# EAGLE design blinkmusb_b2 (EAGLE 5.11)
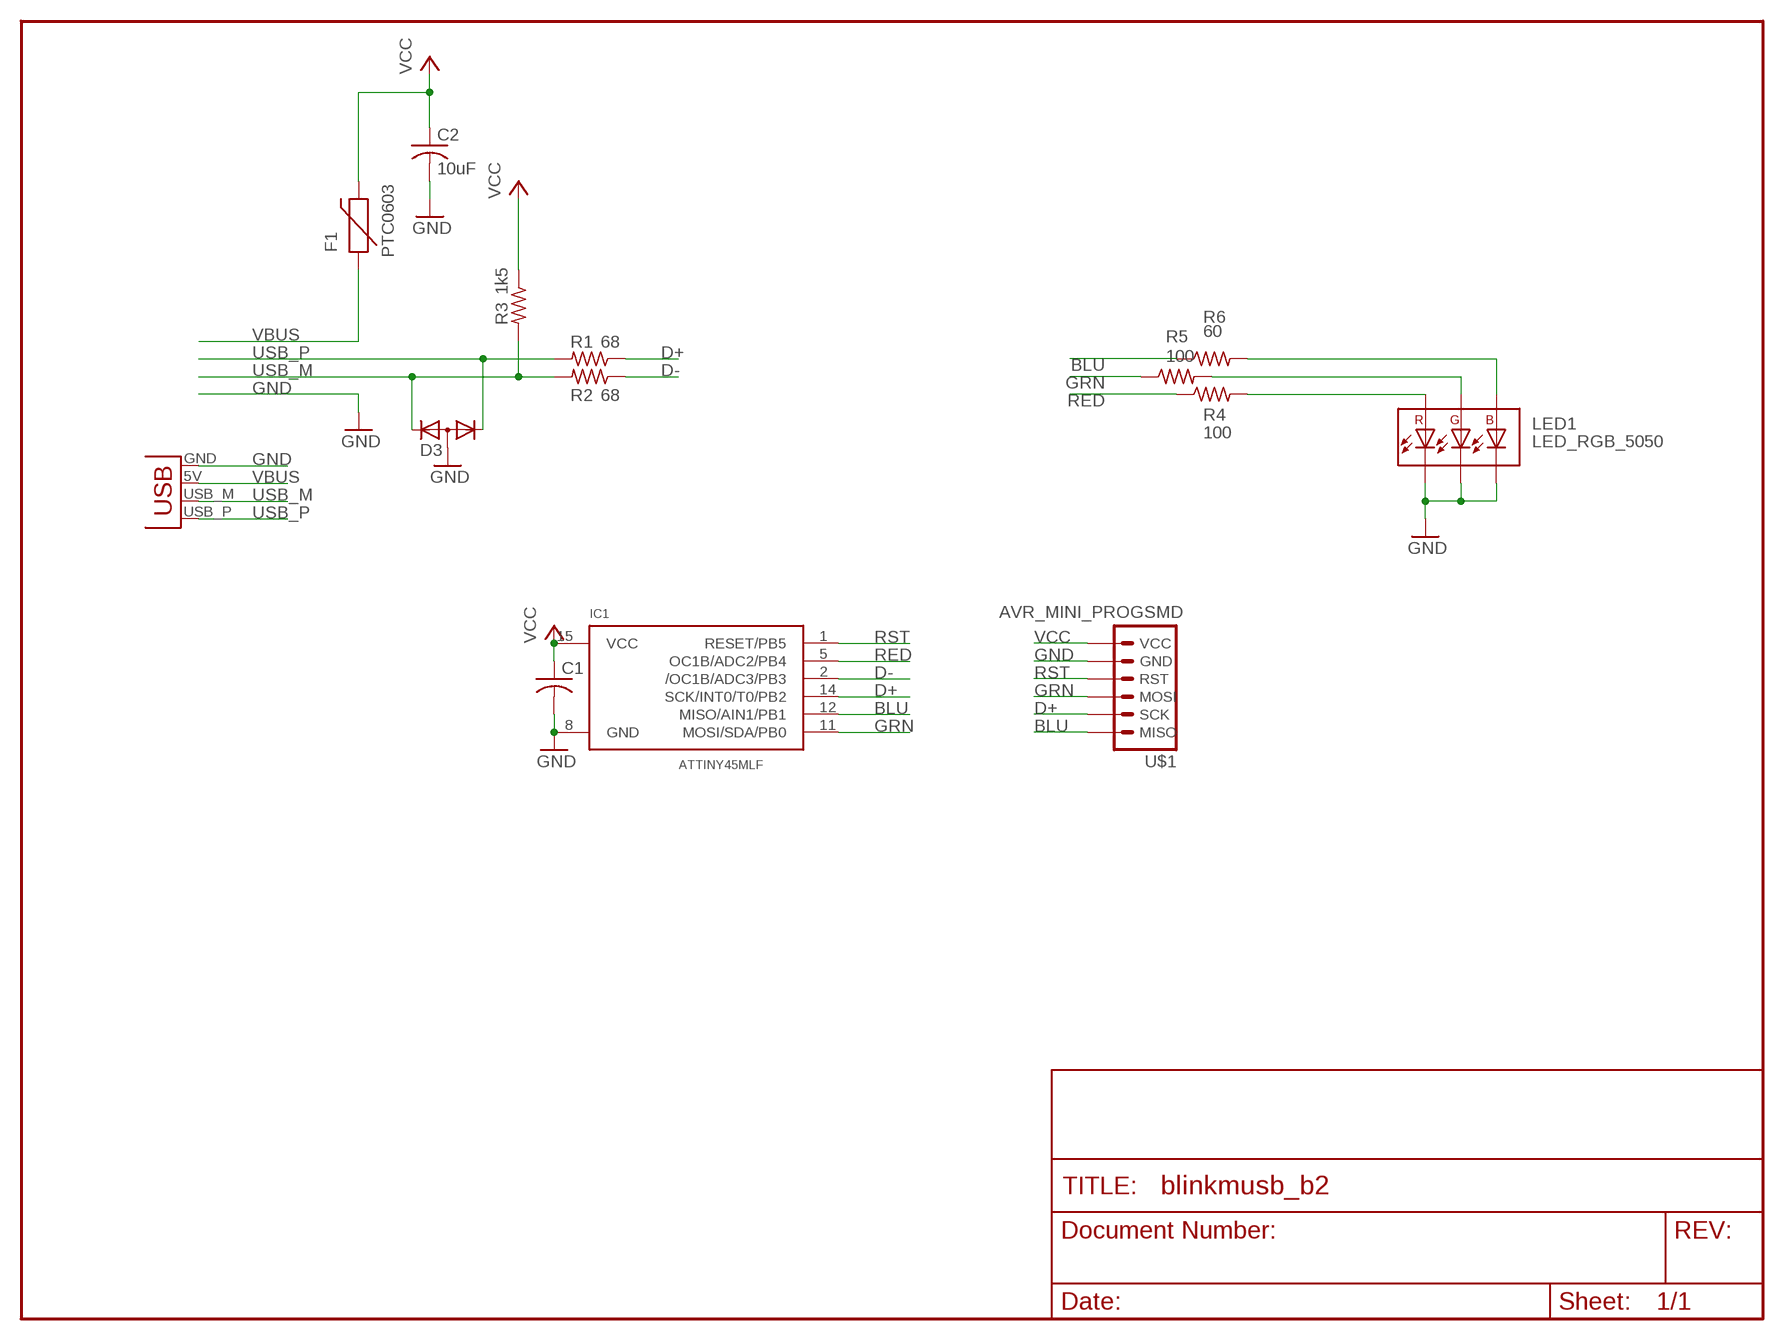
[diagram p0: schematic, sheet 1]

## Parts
C1  C-USC0603  [C0603]
C2  10uF  C-USC0805  [C0805]
D3  DIODE-2CA|ACSOT23  [SOT23]
F1  PTC0603  [0603]
IC1  ATTINY45MLF  [MLF20]
LED1  LED_RGB_5050  [LED_5050]
R1  68  R-US_R0603  [R0603]
R2  68  R-US_R0603  [R0603]
R3  1k5  R-US_R0603  [R0603]
R4  100  R-US_R0603  [R0603]
R5  100  R-US_R0603  [R0603]
R6  60  R-US_R0603  [R0603]
U$1  AVR_MINI_PROGSMD  [AVR_MINI_PROG]
X2  USBPCB  [USB-A-PCB]

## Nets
BLU: IC1.12(MISO/AIN1/PB1) R6.1 U$1.6(MISO)
D+: IC1.14(SCK/INT0/T0/PB2) R1.1 U$1.5(SCK)
D-: IC1.2(/OC1B/ADC3/PB3) R2.1
GND: C1.2 C2.2 D3.3(A) IC1.8(GND) LED1.P$4(C2) LED1.P$5(C1) LED1.P$6(C0) U$1.2(GND) X2.GND
GRN: IC1.11(MOSI/SDA/PB0) R5.1 U$1.4(MOSI)
RBLU: LED1.P$3(A2) R6.2
RED: IC1.5(OC1B/ADC2/PB4) R4.1
RGRN: LED1.P$2(A1) R5.2
RRED: LED1.P$1(A0) R4.2
RST: IC1.1(RESET/PB5) U$1.3(RST)
USB_M: D3.2(K2) R2.2 R3.2 X2.USB_M(D-)
USB_P: D3.1(K1) R1.2 X2.USB_P(D+)
VBUS: F1.1 X2.5V(VBUS)
VCC: C1.1 C2.1 F1.2 IC1.15(VCC) R3.1 U$1.1(VCC)

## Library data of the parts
C1 C2 = rcl:C-US: CAPACITOR, American symbol
D3 = diode:DIODE-2CA|AC: Dual DIODE Cathode-Anode|Anode-Cathode
F1 = SparkFun-20110517:PTC: Resettable Fuse PTC
IC1 = todstuff:ATTINY45
LED1 = todstuff:LED_RGB_5050
R1-R6 = rcl:R-US_: RESISTOR, American symbol
U$1 = SparkFun-20110517:AVR_MINI_PROG
X2 = SparkFun-20110517:USB: USB Connectors USB-B-PTH is fully proven SKU : PRT-00139 USB-miniB is fully proven SKU : PRT-00587 USB-A-PCB is untested. USB-A-H is throughly reviewed, but untested. Spark Fun Electronics SKU : PRT-00437 USB-B-SMT is throughly reviewed, but untested. Needs silkscreen touching up. USB-A-S has not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

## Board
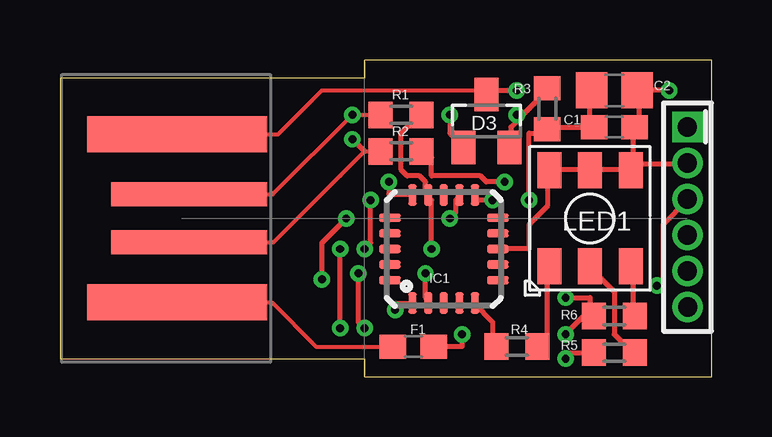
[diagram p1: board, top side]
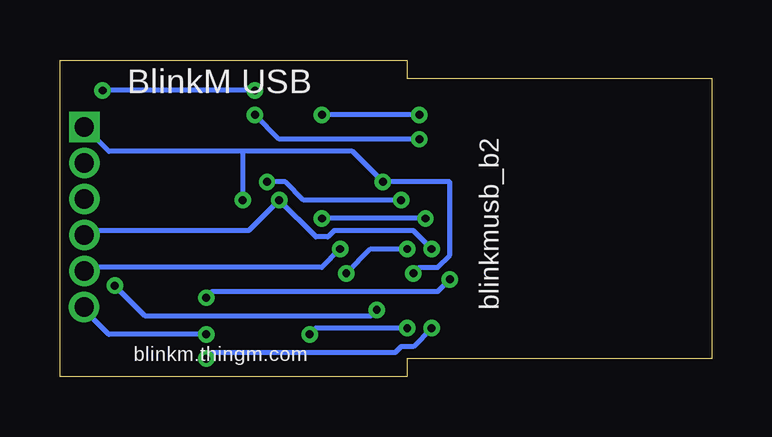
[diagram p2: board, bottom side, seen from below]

Size 27.18 x 13.21 mm. Coordinates in mm from the lower left corner, seen from the top.
Outline: 0,0.76 12.7,0.76 12.7,0 27.18,0 27.18,0.76 27.18,12.45 27.18,13.21 20.32,13.21 12.7,13.21 12.7,12.45 0,12.45 0,0.76
Copper layers (1*16): Top 0.0356mm / dielectric 1.5011mm / Bottom 0.0356mm
Design rules "LaenPCBOrder *": minimum track width 8mil, minimum drill 13mil, track to track 6mil, track to pad 8mil, pad to pad 8mil, via to via 8mil, smd to smd 6mil, copper to edge 15mil, drill to drill 8mil, minimum pad ring 7mil, minimum via ring 7mil, stop-mask expansion 4mil, vias tented up to drill 25mil, thermal gap 10mil
tRestrict: area 0,0 to 10.2,12.7
bRestrict: area 0,0 to 10.2,12.7

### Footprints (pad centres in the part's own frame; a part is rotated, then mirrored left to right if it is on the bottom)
C0603 = smd 1.1 x 1: 1 -0.85,0; 2 0.85,0
C0805 = smd 1.3 x 1.5: 1 -0.95,0; 2 0.95,0
SOT23 = smd 1 x 1.4: 1 -0.95,-1.1; 2 0.95,-1.1; 3 0,1.1
0603 = smd 1.1 x 1: 1 -0.85,0; 2 0.85,0
MLF20 = smd 0.9 x 0.35: 1 -2.25,1.3; 2 -2.25,0.65; 3 -2.25,0; 4 -2.25,-0.65; 5 -2.25,-1.3; 11 2.25,-1.3; 12 2.25,-0.65; 13 2.25,0; 14 2.25,0.65; 15 2.25,1.3 | smd 0.35 x 0.9: 6 -1.3,-2.25; 7 -0.65,-2.25; 8 0,-2.25; 9 0.65,-2.25; 10 1.3,-2.25; 16 1.3,2.25; 17 0.65,2.25; 18 0,2.25; 19 -0.65,2.25; 20 -1.3,2.25
LED_5050 = smd 1 x 1.5: P$1 1.7,2; P$2 0,2; P$3 -1.7,2; P$4 -1.7,-2; P$5 0,-2; P$6 1.7,-2
R0603 = smd 1 x 1.1: 1 -0.85,0; 2 0.85,0
AVR_MINI_PROG = drill 0.8 pad 1.27 square: 1 0,0 | drill 0.8 pad 1.27 round: 2 1.5,0; 3 3,0; 4 4.5,0; 5 6,0; 6 7.5,0.01
USB-A-PCB = smd 7.5 x 1.5: 5V -0.2,-3.5; GND -0.2,3.5 | smd 6.5 x 1: USB_M 0.3,-1; USB_P 0.3,1

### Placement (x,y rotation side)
C1  23.11,10.41 0 top
C2  23.11,11.94 0 top
D3  17.78,10.67 0 top
F1  14.73,1.27 0 top
IC1  16,5.33 90 top
LED1  22.1,6.6 180 top
R1  14.22,10.92 180 top
R2  14.22,9.4 180 top
R3  20.32,11.18 90 top
R4  19.05,1.27 0 top
R5  23.11,1.02 0 top
R6  23.11,2.54 0 top
U$1  26.16,10.41 270 top
X2  5.08,6.6 0 top

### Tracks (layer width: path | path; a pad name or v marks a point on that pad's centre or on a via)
BLU  (via drill 0.33)
  Top 0.203: v16.26,6.6 16.51,6.86 16.51,7.37 IC1.12 | v11.94,6.6 10.92,5.59 v10.92,4.06 | v21.08,3.3 22.1,3.3 22.1,2.79 | 22.1,2.79 22.1,2.54 R6.1 22.1,2.79 | 22.1,2.79 v21.08,1.78
  Bottom 0.203: v11.94,6.6 v16.26,6.6 | v10.92,4.06 11.43,3.56 20.83,3.56 v21.08,3.3 | v21.08,1.78 25.15,1.78 26.16,2.79 U$1.6
D+  (via drill 0.33)
  Top 0.203: R1.1 14.99,10.92 14.22,10.16 14.22,8.64 14.48,8.38 14.99,8.38 15.24,8.13 15.24,7.62 IC1.14 15.49,7.37 v15.49,5.33
  Bottom 0.203: v15.49,5.33 16.26,4.57 26.16,4.57 U$1.5
D-  (via drill 0.33)
  Top 0.203: v15.24,4.32 15.24,3.3 IC1.2 | v12.7,5.33 12.95,5.59 v12.95,7.37 | v18.54,8.13 17.78,8.13 17.53,8.38 15.49,8.38 15.49,9.14 15.24,9.4 R2.1
  Bottom 0.203: v15.24,4.32 14.22,5.33 v12.7,5.33 | v12.95,7.37 17.02,7.37 17.78,8.13 v18.54,8.13
GND  (via drill 0.33)
  Top 0.165: X2.GND 9.09,10.1 10.92,11.94 17.61,11.94 D3.3
  Top 0.203: 24.13,11.94 24.13,10.41 C1.2 23.88,10.41 23.88,8.89 | 24.13,11.94 C2.2 24.13,11.94 | IC1.8 18.29,5.33 19.56,5.33 19.56,6.35 20.32,7.11 20.32,8.38 LED1.P$6 20.57,8.64 22.1,8.64 | 22.1,8.64 LED1.P$5 22.1,8.64 | 22.1,8.64 23.62,8.64 LED1.P$4 | 23.88,8.89 23.88,8.64 LED1.P$4 | 23.88,8.89 26.16,8.89 U$1.2 | 23.88,8.89 LED1.P$4 | v25.4,11.94 24.13,11.94 | v19.05,11.94 17.78,11.94 D3.3
  Bottom 0.203: v19.05,11.94 v25.4,11.94
GRN  (via drill 0.33)
  Top 0.203: v18.03,7.37 17.27,7.37 IC1.11 | v21.08,0.76 21.08,1.02 22.1,1.02 R5.1 | v11.68,2.03 v11.68,5.33
  Bottom 0.203: U$1.4 26.16,6.1 19.3,6.1 v18.03,7.37 16.51,5.84 16,5.84 15.75,6.1 12.45,6.1 v11.68,5.33 | v21.08,0.76 20.83,1.02 13.21,1.02 12.95,1.27 12.45,1.27 v11.68,2.03
RBLU
  Top 0.203: R6.2 23.88,2.54 23.88,4.57 LED1.P$3
RED
  Top 0.203: IC1.5 17.27,3.05 18.03,2.29 18.03,1.27 R4.1
RGRN
  Top 0.203: R5.2 23.88,1.02 23.11,1.78 23.11,3.56 22.1,4.57 LED1.P$2
RRED
  Top 0.203: R4.2 20.07,1.27 20.32,1.52 20.32,4.57 LED1.P$1
RST  (via drill 0.33)
  Top 0.203: v13.97,2.79 13.97,3.05 14.73,3.05 IC1.1 | v24.89,3.81 25.15,4.06 25.15,6.35 26.16,7.37 U$1.3
  Bottom 0.203: v13.97,2.79 14.22,2.54 23.62,2.54 v24.89,3.81
USB_M  (via drill 0.33)
  Top 0.165: X2.USB_M 8.91,5.6 11.68,8.38 12.7,9.4 R2.2
  Top 0.203: 19.3,10.92 18.8,10.41 18.8,9.65 D3.2 | 19.3,10.92 20.32,11.94 R3.2 | v19.05,10.92 19.3,10.92 | 12.7,9.4 v12.19,9.91
  Bottom 0.203: v19.05,10.92 18.03,9.91 v12.19,9.91
USB_P  (via drill 0.33)
  Top 0.165: 13.21,10.92 R1.2 v12.19,10.92 8.87,7.6 X2.USB_P
  Top 0.203: v16.26,10.92 16.26,10.16 16.76,9.65 D3.1
  Bottom 0.203: v12.19,10.92 v16.26,10.92
VBUS
  Top 0.165: X2.5V 8.83,3.1 10.67,1.27 F1.1
VCC  (via drill 0.33)
  Top 0.203: 22.1,10.41 20.32,10.41 R3.1 20.32,10.16 19.56,10.16 v19.56,7.37 | 22.1,10.41 C1.1 22.1,10.41 | 22.1,10.41 22.1,11.94 C2.1 | v13.72,8.13 13.72,7.62 14.73,7.62 IC1.15 | v16.76,1.78 16.76,1.27 15.75,1.27 F1.2 | v12.7,2.03 12.45,2.29 v12.45,4.32
  Bottom 0.203: 19.56,9.4 25.15,9.4 U$1.1 | 19.56,9.4 14.99,9.4 v13.72,8.13 10.92,8.13 10.92,5.08 11.43,4.57 12.19,4.57 v12.45,4.32 | v16.76,1.78 16.51,2.03 v12.7,2.03 | 19.56,9.4 v19.56,7.37

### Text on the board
bPlace: BlinkM USB | blinkmusb_b2 | blinkm.thingm.com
